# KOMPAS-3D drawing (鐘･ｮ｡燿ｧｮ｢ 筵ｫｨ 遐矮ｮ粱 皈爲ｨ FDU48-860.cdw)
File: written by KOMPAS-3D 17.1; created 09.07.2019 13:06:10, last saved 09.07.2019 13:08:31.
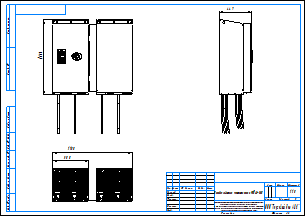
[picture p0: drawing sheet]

Sheet 1: A3, landscape

Title block, sheet 1: name: Преобразователи частоты серии FDU48-860; sheets: 1; sheet format: A3; stored path: \\adlc.lan\data\АДЛ_ПКД\3D-модели\Поставщики\Оборудование Emotron\Преобразователи частоты\Серия FDU 2.0\KOMPAS 2D\Преобразователи частоты серии FDU48-860.cdw

Views: Вид 1
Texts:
  user
  CONTINUOUS_RGB_0_0_0_THICK_0.18
  POLYLINE_STYLE_0.18_RGB_0_0_0
  Рама для чертежей
  Лит-Масса-Масштаб
  Материал-Предприятие
  Масштаб
  Изм.
  Лист
  № докум.
  Подп.
  Дата
  Лит.
  Разраб.
  Пров.
  Т.контр.
  Листов
  Внимание! Данный продукт является объектом авторского права ООО «Торговый Дом АДЛ».
  Запрещается изменение, копирование, распространение
  (в том числе путем копирования на другие сайты и ресурсы в Интернете)
  или любое иное использование информации и объектов без предварительного
  согласия правообладателя (ООО «Торговый Дом АДЛ»).
  Н.контр.
  Утв.
  ООО "Торговый дом АДЛ"
  Изменение
  Номер документа
  Подпись
  Обозначение документа
  Наименование изделия
  Масса изделия по ГОСТ 2.109-73
  Порядковый номер листа
  Общее количество листов в документе
  Характер работы, выполненной лицом, подписавшим документ
  Наименование или индекс предприятия, выпускающего документ
  Инв. № подл.
  Подп. и дата
  Взам. инв. №
  Инв. № дубл.
  Инвентарный номер подлинника по ГОСТ 2.501-68
  Подпись принявшего подлинник в отдел технической документации
  Инвентарный номер подлинника, взамен которого выпущен данный подлинник
  Инвентарный номер дубликата по ГОСТ 2.502-68
  Подпись принявшего дубликат в отдел технической документации
  Справ. №
  Перв. примен.
  Обозначение документа, взамен или на основании которого выпущен данный документ
  Обозначение документа, в котором впервые записан данный документ
  Подпись лица, копировавшего чертеж
  Обозначение формата листа
  !Рама для чертежа
Dimensions and other numbers on the sheet: 1100; 500; 1036; 449; 1:10; 1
